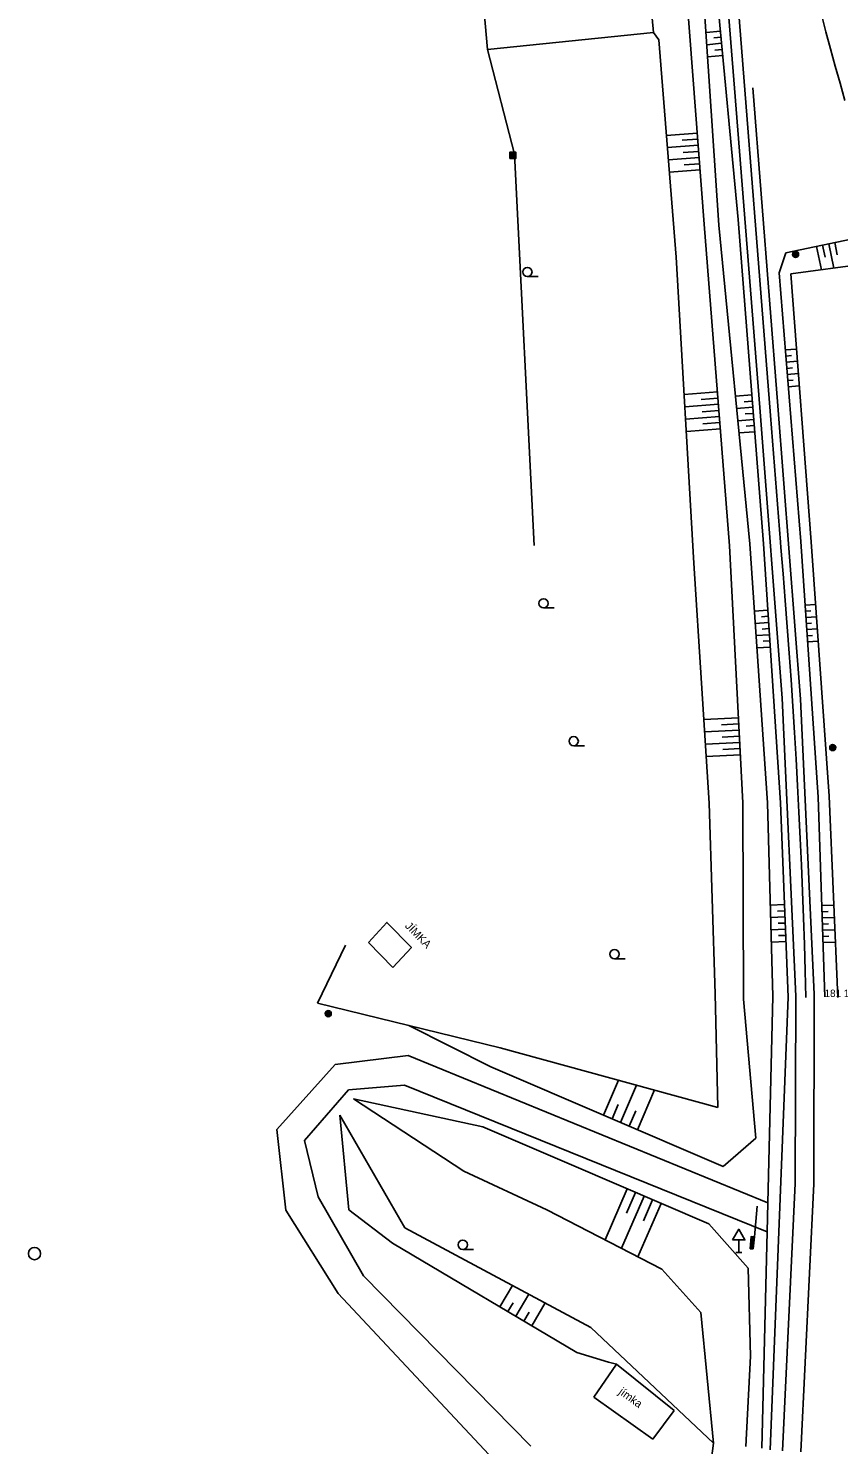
# Model space of a CAD drawing. Extents: x -539244 to -537359, y -1183785 to -1181851.
# Drawn here: x -537724.2 to -537658.5, y -1182803.4 to -1182688.3 of the extents above; entities that cross this region are included whole.
import ezdxf

# ---------------------------------------------------------------- set-up
doc = ezdxf.new("R2010")
doc.units = 0
for name, color, linetype in [('Vrstva 10', 7, 'Continuous'), ('Vrstva 11', 7, 'Continuous'), ('Vrstva 12', 7, 'Continuous'), ('Vrstva 13', 7, 'Continuous'), ('Vrstva 14', 7, 'Continuous'), ('Vrstva 15', 7, 'Continuous'), ('Vrstva 22', 7, 'Continuous'), ('Vrstva 25', 7, 'Continuous'), ('Vrstva 27', 7, 'Continuous'), ('Vrstva 33', 7, 'Continuous'), ('Vrstva 34', 7, 'Continuous'), ('Vrstva 36', 7, 'Continuous'), ('Vrstva 40', 7, 'Continuous'), ('Vrstva 7', 7, 'Continuous')]:
    doc.layers.add(name, color=color, linetype=linetype)

msp = doc.modelspace()

# ---------------------------------------------------------------- linework, layer by layer
at = {"layer": 'Vrstva 10'}
for p, q in [((-537704.08, -1182777.76), (-537699.33, -1182772.5)), ((-537699.33, -1182772.5), (-537693.42, -1182771.76)), ((-537693.42, -1182771.76), (-537664.219, -1182783.733)), ((-537701.83, -1182778.67), (-537698.25, -1182774.54)), ((-537698.25, -1182774.54), (-537693.71, -1182774.16)), ((-537693.71, -1182774.16), (-537664.276, -1182786.086)), ((-537703.34, -1182784.31), (-537704.08, -1182777.76)), ((-537700.73, -1182783.25), (-537701.83, -1182778.67)), ((-537699.1, -1182791.1), (-537703.34, -1182784.31)), ((-537697.05, -1182789.65), (-537700.73, -1182783.25)), ((-537683.44, -1182803.48), (-537697.05, -1182789.65)), ((-537686.04, -1182805.03), (-537699.1, -1182791.1))]:
    msp.add_line(p, q, dxfattribs=at)
at = {"layer": 'Vrstva 11'}
for p, q in [((-537694.65, -1182764.62), (-537696.63, -1182762.59)), ((-537678.33, -1182799.52), (-537676.5, -1182796.82)), ((-537676.5, -1182796.82), (-537671.81, -1182800.59)), ((-537673.54, -1182802.93), (-537678.33, -1182799.52)), ((-537671.81, -1182800.59), (-537673.54, -1182802.93))]:
    msp.add_line(p, q, dxfattribs=at)
msp.add_lwpolyline([(-537696.63, -1182762.59), (-537695.13, -1182760.95), (-537693.15, -1182762.98), (-537694.65, -1182764.62)], dxfattribs=at)
at = {"layer": 'Vrstva 12'}
for p, q in [((-537666.92, -1182693.19), (-537668.74, -1182669.88)), ((-537664.87, -1182719.14), (-537666.92, -1182693.19)), ((-537663.39, -1182718.99), (-537665.43, -1182693.169)), ((-537663.05, -1182742.73), (-537664.87, -1182719.14)), ((-537661.552, -1182742.81), (-537663.39, -1182718.99)), ((-537661.95, -1182766.93), (-537663.05, -1182742.73)), ((-537660.44, -1182766.79), (-537661.552, -1182742.81)), ((-537661.98, -1182782.16), (-537661.95, -1182766.93)), ((-537660.47, -1182782.18), (-537660.44, -1182766.79)), ((-537663.03, -1182803.86), (-537661.98, -1182782.16)), ((-537661.52, -1182803.96), (-537660.47, -1182782.18))]:
    msp.add_line(p, q, dxfattribs=at)
at = {"layer": 'Vrstva 13'}
for p, q in [((-537667.068, -1182680.693), (-537664.002, -1182719.792)), ((-537664.002, -1182719.792), (-537663.194, -1182730.081))]:
    msp.add_line(p, q, dxfattribs=at)
for points in [[(-537660.58, -1182684.416), (-537660.227, -1182685.819), (-537659.866, -1182687.22), (-537659.497, -1182688.619), (-537659.121, -1182690.016), (-537658.737, -1182691.411), (-537658.345, -1182692.804), (-537657.945, -1182694.195)], [(-537662.631, -1182736.947), (-537662.798, -1182734.801), (-537662.973, -1182732.655), (-537663.156, -1182730.51), (-537663.194, -1182730.081)], [(-537661.914, -1182747.689), (-537662.041, -1182745.539), (-537662.177, -1182743.39), (-537662.32, -1182741.242), (-537662.471, -1182739.094), (-537662.631, -1182736.947)], [(-537661.397, -1182758.441), (-537661.485, -1182756.29), (-537661.58, -1182754.139), (-537661.683, -1182751.988), (-537661.795, -1182749.838), (-537661.914, -1182747.689)], [(-537661.127, -1182767.049), (-537661.183, -1182764.897), (-537661.246, -1182762.745), (-537661.318, -1182760.593), (-537661.397, -1182758.441)]]:
    msp.add_lwpolyline(points, dxfattribs=at)
at = {"layer": 'Vrstva 14'}
for p, q in [((-537669.985, -1182677.373), (-537668.182, -1182704.315)), ((-537666.613, -1182703.875), (-537669.107, -1182677.372)), ((-537671.43, -1182677.39), (-537669.383, -1182704.245)), ((-537669.383, -1182704.245), (-537667.311, -1182730.373)), ((-537668.182, -1182704.315), (-537665.68, -1182730.218)), ((-537664.575, -1182730.197), (-537666.613, -1182703.875)), ((-537656.288, -1182705.223), (-537662.735, -1182706.564)), ((-537662.735, -1182706.564), (-537663.298, -1182708.194)), ((-537663.298, -1182708.194), (-537661.528, -1182730.023)), ((-537662.334, -1182708.281), (-537656.297, -1182707.471)), ((-537660.705, -1182730.033), (-537662.334, -1182708.281)), ((-537665.68, -1182730.218), (-537664.249, -1182751.235)), ((-537663.17, -1182751.23), (-537664.575, -1182730.197)), ((-537661.528, -1182730.023), (-537660.132, -1182750.767)), ((-537659.234, -1182750.712), (-537660.705, -1182730.033)), ((-537667.311, -1182730.373), (-537666.245, -1182751.235)), ((-537660.132, -1182750.767), (-537659.569, -1182766.988)), ((-537658.538, -1182767.044), (-537659.234, -1182750.712)), ((-537666.245, -1182751.235), (-537666.18, -1182767.176)), ((-537664.249, -1182751.235), (-537663.814, -1182766.978)), ((-537662.549, -1182767.01), (-537663.17, -1182751.23)), ((-537664.219, -1182783.733), (-537663.814, -1182766.978)), ((-537664.03, -1182803.78), (-537662.549, -1182767.01)), ((-537666.18, -1182767.176), (-537665.19, -1182778.47)), ((-537686.71, -1182772.68), (-537693.35, -1182769.315)), ((-537667.83, -1182780.77), (-537686.71, -1182772.68)), ((-537697.85, -1182775.27), (-537687.35, -1182777.55)), ((-537688.88, -1182781.16), (-537697.85, -1182775.27)), ((-537698.97, -1182776.6), (-537693.67, -1182785.75)), ((-537698.97, -1182776.6), (-537698.22, -1182784.3)), ((-537687.35, -1182777.55), (-537680.15, -1182780.63)), ((-537665.19, -1182778.47), (-537667.83, -1182780.77)), ((-537680.15, -1182780.63), (-537669.01, -1182785.44)), ((-537682.14, -1182784.29), (-537688.88, -1182781.16)), ((-537698.22, -1182784.3), (-537694.68, -1182786.99)), ((-537672.81, -1182789.11), (-537682.14, -1182784.29)), ((-537664.276, -1182786.086), (-537664.219, -1182783.733)), ((-537669.01, -1182785.44), (-537665.82, -1182789.03)), ((-537693.67, -1182785.75), (-537678.57, -1182793.85)), ((-537664.7, -1182803.65), (-537664.276, -1182786.086)), ((-537694.68, -1182786.99), (-537679.73, -1182795.88)), ((-537669.66, -1182792.64), (-537672.81, -1182789.11)), ((-537665.82, -1182789.03), (-537665.63, -1182796.18)), ((-537668.63, -1182803.25), (-537669.66, -1182792.64)), ((-537678.57, -1182793.85), (-537668.63, -1182803.25)), ((-537665.63, -1182796.18), (-537665.99, -1182803.51)), ((-537671.69, -1182826.91), (-537668.63, -1182803.25))]:
    msp.add_line(p, q, dxfattribs=at)
msp.add_lwpolyline([(-537679.73, -1182795.88), (-537677.15, -1182796.66), (-537676.5, -1182796.82)], dxfattribs=at)
at = {"layer": 'Vrstva 15'}
for p, q in [((-537668.054, -1182688.563), (-537669.23, -1182688.673)), ((-537667.96, -1182689.558), (-537669.162, -1182689.671)), ((-537668.008, -1182689.061), (-537668.602, -1182689.116)), ((-537667.866, -1182690.554), (-537669.096, -1182690.67)), ((-537667.914, -1182690.056), (-537668.522, -1182690.113)), ((-537669.948, -1182696.844), (-537672.434, -1182697.033)), ((-537669.872, -1182697.841), (-537672.354, -1182698.03)), ((-537669.91, -1182697.343), (-537671.152, -1182697.437)), ((-537669.796, -1182698.838), (-537672.276, -1182699.027)), ((-537669.834, -1182698.34), (-537671.074, -1182698.434)), ((-537669.72, -1182699.835), (-537672.196, -1182700.024)), ((-537669.758, -1182699.337), (-537670.996, -1182699.431)), ((-537660.25, -1182706.047), (-537659.854, -1182707.948)), ((-537659.76, -1182705.945), (-537659.558, -1182706.914)), ((-537659.27, -1182705.844), (-537658.86, -1182707.815)), ((-537658.78, -1182705.742), (-537658.572, -1182706.745)), ((-537662.79, -1182714.458), (-537661.878, -1182714.384)), ((-537662.75, -1182714.957), (-537662.296, -1182714.92)), ((-537662.71, -1182715.455), (-537661.802, -1182715.382)), ((-537662.67, -1182715.954), (-537662.218, -1182715.917)), ((-537662.63, -1182716.452), (-537661.728, -1182716.379)), ((-537662.588, -1182716.95), (-537662.14, -1182716.914)), ((-537662.548, -1182717.449), (-537661.654, -1182717.376)), ((-537668.302, -1182717.871), (-537670.998, -1182718.085)), ((-537668.264, -1182718.369), (-537669.616, -1182718.477)), ((-537665.512, -1182718.114), (-537666.84, -1182718.217)), ((-537665.472, -1182718.612), (-537666.132, -1182718.664)), ((-537668.224, -1182718.868), (-537670.94, -1182719.083)), ((-537668.144, -1182719.865), (-537670.884, -1182720.082)), ((-537668.184, -1182719.366), (-537669.548, -1182719.474)), ((-537665.434, -1182719.111), (-537666.744, -1182719.212)), ((-537665.396, -1182719.609), (-537666.046, -1182719.66)), ((-537668.066, -1182720.862), (-537670.826, -1182721.08)), ((-537668.106, -1182720.363), (-537669.48, -1182720.472)), ((-537665.356, -1182720.108), (-537666.648, -1182720.208)), ((-537665.318, -1182720.607), (-537665.958, -1182720.656)), ((-537665.28, -1182721.105), (-537666.552, -1182721.203)), ((-537664.216, -1182735.592), (-537665.31, -1182735.665)), ((-537661.182, -1182735.181), (-537660.344, -1182735.124)), ((-537661.148, -1182735.68), (-537660.728, -1182735.651)), ((-537664.148, -1182736.59), (-537665.242, -1182736.663)), ((-537664.182, -1182736.091), (-537664.728, -1182736.127)), ((-537664.116, -1182737.089), (-537664.662, -1182737.125)), ((-537661.114, -1182736.178), (-537660.272, -1182736.122)), ((-537661.08, -1182736.677), (-537660.658, -1182736.649)), ((-537661.048, -1182737.176), (-537660.202, -1182737.119)), ((-537664.082, -1182737.587), (-537665.174, -1182737.66)), ((-537664.048, -1182738.086), (-537664.594, -1182738.123)), ((-537661.014, -1182737.675), (-537660.59, -1182737.647)), ((-537660.98, -1182738.174), (-537660.13, -1182738.117)), ((-537664.016, -1182738.585), (-537665.106, -1182738.658)), ((-537666.598, -1182744.336), (-537669.406, -1182744.479)), ((-537666.572, -1182744.835), (-537667.974, -1182744.907)), ((-537666.548, -1182745.335), (-537669.344, -1182745.478)), ((-537666.496, -1182746.333), (-537669.282, -1182746.476)), ((-537666.522, -1182745.834), (-537667.918, -1182745.905)), ((-537666.446, -1182747.332), (-537669.218, -1182747.474)), ((-537666.47, -1182746.833), (-537667.86, -1182746.904)), ((-537662.844, -1182759.504), (-537664.02, -1182759.55)), ((-537662.824, -1182760.004), (-537663.416, -1182760.027)), ((-537659.826, -1182759.587), (-537658.858, -1182759.553)), ((-537659.81, -1182760.086), (-537659.322, -1182760.07)), ((-537662.806, -1182760.503), (-537663.992, -1182760.55)), ((-537662.786, -1182761.003), (-537663.382, -1182761.026)), ((-537659.792, -1182760.586), (-537658.816, -1182760.552)), ((-537659.774, -1182761.086), (-537659.284, -1182761.069)), ((-537662.766, -1182761.502), (-537663.964, -1182761.55)), ((-537662.746, -1182762.002), (-537663.348, -1182762.026)), ((-537659.758, -1182761.586), (-537658.772, -1182761.551)), ((-537659.74, -1182762.085), (-537659.246, -1182762.068)), ((-537662.726, -1182762.502), (-537663.936, -1182762.549)), ((-537659.722, -1182762.585), (-537658.73, -1182762.551)), ((-537677.543, -1182776.608), (-537676.324, -1182773.761)), ((-537676.164, -1182777.199), (-537674.863, -1182774.161)), ((-537674.786, -1182777.79), (-537673.402, -1182774.561)), ((-537676.853, -1182776.903), (-537676.349, -1182775.727)), ((-537675.475, -1182777.494), (-537674.938, -1182776.241)), ((-537675.638, -1182782.578), (-537677.428, -1182786.724)), ((-537674.26, -1182783.173), (-537676.092, -1182787.415)), ((-537674.949, -1182782.876), (-537675.674, -1182784.553)), ((-537672.883, -1182783.768), (-537674.756, -1182788.105)), ((-537673.572, -1182783.47), (-537674.313, -1182785.186)), ((-537685.962, -1182792.174), (-537684.93, -1182790.438)), ((-537684.673, -1182792.941), (-537683.607, -1182791.148)), ((-537685.318, -1182792.557), (-537684.898, -1182791.852)), ((-537683.384, -1182793.707), (-537682.284, -1182791.858)), ((-537684.028, -1182793.324), (-537683.595, -1182792.595))]:
    msp.add_line(p, q, dxfattribs=at)
at = {"layer": 'Vrstva 25'}
for points in [[(-537685.16, -1182698.91), (-537684.66, -1182698.91), (-537684.66, -1182698.41), (-537685.16, -1182698.41)], [(-537685.11, -1182698.86), (-537684.71, -1182698.86), (-537684.71, -1182698.46), (-537685.11, -1182698.46)], [(-537685.06, -1182698.81), (-537684.76, -1182698.81), (-537684.76, -1182698.51), (-537685.06, -1182698.51)], [(-537685.01, -1182698.76), (-537684.81, -1182698.76), (-537684.81, -1182698.56), (-537685.01, -1182698.56)], [(-537684.96, -1182698.71), (-537684.86, -1182698.71), (-537684.86, -1182698.61), (-537684.96, -1182698.61)]]:
    msp.add_lwpolyline(points, close=True, dxfattribs=at)
for centre, radius in [((-537661.958, -1182706.696), 0.25), ((-537661.958, -1182706.696), 0.2), ((-537661.958, -1182706.696), 0.15), ((-537661.958, -1182706.696), 0.1), ((-537661.958, -1182706.696), 0.05), ((-537658.935, -1182746.75), 0.25), ((-537658.935, -1182746.75), 0.2), ((-537658.935, -1182746.75), 0.15), ((-537658.935, -1182746.75), 0.1), ((-537658.935, -1182746.75), 0.05), ((-537699.9, -1182768.36), 0.25), ((-537699.9, -1182768.36), 0.2), ((-537699.9, -1182768.36), 0.15), ((-537699.9, -1182768.36), 0.1), ((-537699.9, -1182768.36), 0.05)]:
    msp.add_circle(centre, radius, dxfattribs=at)
at = {"layer": 'Vrstva 27'}
msp.add_circle((-537723.75, -1182787.85), 0.5, dxfattribs=at)
at = {"layer": 'Vrstva 33'}
msp.add_line((-537665.303, -1182786.474), (-537665.085, -1182783.983), dxfattribs=at)
for points in [[(-537665.39, -1182787.47), (-537665.303, -1182786.474), (-537665.552, -1182786.452), (-537665.639, -1182787.448)], [(-537665.435, -1182787.416), (-537665.357, -1182786.519), (-537665.506, -1182786.506), (-537665.585, -1182787.403)], [(-537665.481, -1182787.362), (-537665.411, -1182786.565), (-537665.461, -1182786.56), (-537665.531, -1182787.357)]]:
    msp.add_lwpolyline(points, close=True, dxfattribs=at)
at = {"layer": 'Vrstva 34'}
for p, q in [((-537666.82, -1182787.75), (-537666.32, -1182787.75)), ((-537666.57, -1182786.732), (-537666.57, -1182787.75))]:
    msp.add_line(p, q, dxfattribs=at)
msp.add_lwpolyline([(-537667.07, -1182786.732), (-537666.07, -1182786.732), (-537666.57, -1182785.866)], close=True, dxfattribs=at)
at = {"layer": 'Vrstva 36'}
for p, q in [((-537683.73, -1182708.505), (-537682.855, -1182708.505)), ((-537682.42, -1182735.415), (-537681.545, -1182735.415)), ((-537679.97, -1182746.605), (-537679.095, -1182746.605)), ((-537676.66, -1182763.905), (-537675.785, -1182763.905)), ((-537688.98, -1182787.505), (-537688.105, -1182787.505))]:
    msp.add_line(p, q, dxfattribs=at)
for centre in [(-537683.73, -1182708.13), (-537682.42, -1182735.04), (-537679.97, -1182746.23), (-537676.66, -1182763.53), (-537688.98, -1182787.13)]:
    msp.add_circle(centre, 0.375, dxfattribs=at)
at = {"layer": 'Vrstva 7'}
for p, q in [((-537686.96, -1182690.06), (-537688.66, -1182671.17)), ((-537673.506, -1182688.684), (-537674.402, -1182678.558)), ((-537686.96, -1182690.06), (-537673.506, -1182688.684)), ((-537673.051, -1182689.285), (-537673.506, -1182688.684)), ((-537671.644, -1182706.939), (-537673.051, -1182689.285)), ((-537684.78, -1182698.55), (-537686.96, -1182690.06)), ((-537683.19, -1182730.33), (-537684.78, -1182698.55)), ((-537670.205, -1182731.771), (-537671.644, -1182706.939)), ((-537668.978, -1182751.279), (-537670.205, -1182731.771)), ((-537668.476, -1182766.746), (-537668.978, -1182751.279)), ((-537700.77, -1182767.5), (-537698.494, -1182762.79)), ((-537668.476, -1182766.746), (-537668.26, -1182775.97)), ((-537693.35, -1182769.315), (-537700.77, -1182767.5)), ((-537685.93, -1182771.13), (-537693.35, -1182769.315)), ((-537668.26, -1182775.97), (-537685.93, -1182771.13))]:
    msp.add_line(p, q, dxfattribs=at)

# ---------------------------------------------------------------- texts
at = {"layer": 'Vrstva 22'}
msp.add_text('181 16 ', height=0.6, dxfattribs=at).set_placement((-537659.604, -1182767.008))
at = {"layer": 'Vrstva 40'}
for s, rotation, p in [('JÍMKA', 314.28563, (-537693.715, -1182761.283)), ('jímka', 324.55294, (-537676.376, -1182799.202))]:
    msp.add_text(s, height=0.65, rotation=rotation, dxfattribs=at).set_placement(p)

doc.saveas('drawing.dxf')
